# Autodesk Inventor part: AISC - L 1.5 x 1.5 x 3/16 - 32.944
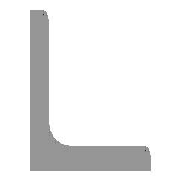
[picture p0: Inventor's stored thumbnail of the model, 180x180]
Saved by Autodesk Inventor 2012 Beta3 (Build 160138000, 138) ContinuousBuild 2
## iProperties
_CCFamilyMember: 5
_CCFamilyDisplayName: ANSI L (Equal angles) - Angle Steel
_FrameMemberDoc: Frame Member File
_Version: 15.0.0
_GetPNFromCC: 1
Created: 2010-11
Part Number: AISC - L 1.5 x 1.5 x 3/16 - 32.944
Material: Steel, Mild
Description: Angle Steel
Document SubType Name: Modeling
Standard: ANSI
Designer: Beta-8540w
Standards Organization: ANSI
Language: en-US
Size Designation: L 1.5 x 1.5 x 3/16
Categories: <MemberInstance><Categories><Category DisplayName="Structural Shapes" InternalName="089c4875-fa83-4c05-b084-43b9cc11f5ed" Mnemonic="GRDR"><CategoryParameter Dis
Stock Number: L 1.5 x 1.5 x 3/16
Density: 7.86 g/cm^3
G_L: 32.944 in
G_W: 1.500 in
G_H: 1.500 in
IsCustomPart: 1
Author: Beta-8540w
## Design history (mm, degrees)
node "Start plane"
node "End plane"
sketch "Sketch"
  geometry: L1 (38.1, 0)-(0, 0); L2 (0, 0)-(0, 38.1); L3 (0, 38.1)-(2.476, 38.1); L4 (4.762, 35.814)-(4.762, 9.589); L5 (9.588, 4.763)-(35.814, 4.763); L6 (38.1, 2.477)-(38.1, 0); L7 (0, -11.041)-(0, 31.538); L8 (-11.041, 0)-(31.538, 0); L9 (0, 48.496)-(0, -20.964) reference; L10 (-20.964, 0)-(48.496, 0) reference; A1 r 4.826 centre (9.588, 9.589) between (4.762, 9.589) and (9.588, 4.763); A2 r 2.286 centre (2.476, 35.814) between (4.762, 35.814) and (2.476, 38.1); A3 r 2.286 centre (35.814, 2.477) between (38.1, 2.477) and (35.814, 4.763); 3 further points
  constraints: 16 end point, 6 point on circle, 6 point on line, 6 tangent, 4 parallel, 3 centre point, 2 collinear, 1 equal radius, 1 horizontal, 1 perpendicular
  dimensions: "d0" = 38.1 distance between parallel lines of L6 L2 (= G_H); "d1" = 38.1 distance between parallel lines of L3 L1 (= G_H); "d2" = 4.7625 distance between parallel lines of L2 L4 (= G_T); "d3" = 4.7625 distance between parallel lines of L1 L5 (= G_T); "d10" = 0 distance between parallel lines of L7 L2 (computed from ex); "d11" = 0 distance between parallel lines of L8 L1 (computed from d10); "d14" = 4.826 radius of A1 (= G_IR); "d15" = 2.286 radius of A2 (= G_ER)
extrude "Body" new body sketch "Sketch" stored distance "d4" = 836.76542 (= G_L); taper "d5" = 0 deg
node "Driven Length"
  sketch "Sketch3"
    geometry: L1 (0, 0)-(10, 0) reference
    constraints: 2 end point, 1 horizontal
  workplane "Work Plane3"
  sketch "Sketch4"
    geometry: L1 (-2, 0)-(12, 0) reference; L2 (-2, 836.765)-(12, 836.765) reference
    dimensions: "d17" = 836.76542 distance between parallel lines of L1 L2 (derived)
body "Solid1"
other parameters: "G_H" = 38.1 [user parameter; used in 2 equation terms], "G_T" = 4.7625 [user parameter; used in 2 equation terms], "G_ER" = 2.286 [user parameter; used in 1 equation term], "G_IR" = 4.826 [user parameter; used in 1 equation term], "G_L" = 836.76542 (= d17) [user parameter; used in 1 equation term], "ex" = 0 [user parameter; used in 1 equation term], "G_OFFSET_START" = 0 [user parameter; used in 1 equation term], "G_OFFSET_END" = 0 [user parameter; used in 1 equation term], "d12" = 0 (computed from G_OFFSET_START), "d13" = 836.76542 (= G_OFFSET_END + B_L), "B_L" = 836.76542 [user parameter; used in 1 equation term], "d16" = 90 deg, "MAS" = 0.26787 [user parameter]
